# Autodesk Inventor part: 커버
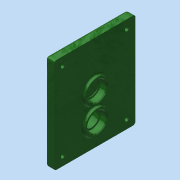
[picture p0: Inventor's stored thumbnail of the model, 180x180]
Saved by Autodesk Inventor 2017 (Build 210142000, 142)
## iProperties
Created: 2016-02
Part Number: 커버
Material: 알루미늄 6061
Document SubType Name: Modeling
Designer: mduedu
Density: 2.71 g/cm^3
Appearance: 매끄러움 - 짙은 산림 녹색
Mass: 271.622 g
Surface Area: 265.357 cm^2
Volume: 100.23 cm^3
Author: mduedu
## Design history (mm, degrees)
sketch "스케치1"
  geometry: L1 (63, 47)-(-47, 47); L2 (-47, 47)-(-47, -47); L3 (-47, -47)-(63, -47); L4 (63, -47)-(63, 47); 2 further points
  constraints: 8 end point, 2 parallel, 1 horizontal, 1 horizontal alignment, 1 midpoint, 1 perpendicular
  dimensions: "d102" = 94 distance of L3.end L1.start; "d104" = 47 distance from line of L2 point (0, 0); "d105" = 110 distance of L1.start L1.end
extrude "돌출1" new body sketch "스케치1" distance "d1" = 10; taper "d2" = 0 deg
sketch "스케치2"
  geometry: C1 r 14 at (0, 11); 1 further point
  constraints: 1 centre point, 1 vertical alignment
  dimensions: "d3" = 28 diameter of C1; "d6" = 11 distance of C1.centre point (0, 0)
extrude "돌출2" join sketch "스케치2" distance "d7" = 3; taper "d8" = 0 deg
sketch "스케치3"
  geometry: C1 r 14 at (0, -20); 1 further point
  constraints: 1 centre point, 1 vertical alignment
  dimensions: "d9" = 28 diameter of C1; "d10" = 20 distance of C1.centre point (0, 0)
extrude "돌출3" join sketch "스케치3" distance "d11" = 3; taper "d12" = 0 deg
hole "구멍1" diameter "d15" = 22; stored, may be unused: countersink angle "d19" = 90 deg, drill point angle "d21" = 0 deg; dims "d13" = 10, "d14" = 10, "d16" = 6, "d17" = 4, "d18" = 2, "d20" = 7
hole "구멍2" diameter "d24" = 18; stored, may be unused: countersink angle "d28" = 90 deg, drill point angle "d30" = 0 deg; dims "d22" = 10, "d23" = 10, "d25" = 6, "d26" = 4, "d27" = 2, "d29" = 1
hole "구멍3" diameter "d33" = 22; stored, may be unused: countersink angle "d37" = 90 deg, drill point angle "d39" = 0 deg; dims "d34" = 6, "d35" = 4, "d36" = 2, "d38" = 7, "d73" = 10, "d74" = 10
sketch "스케치4"
  geometry: C1 r 14 at (0, -20) reference; C2 r 18 at (0, -20); 1 further point
  constraints: 1 centre point, 1 coincident
  dimensions: "d40" = 36 diameter of C2
extrude "돌출4" join sketch "스케치4" distance "d41" = 4; taper "d42" = 0 deg
hole "구멍4" diameter "d45" = 22; stored, may be unused: countersink angle "d49" = 90 deg, drill point angle "d51" = 0 deg; dims "d43" = 10, "d44" = 10, "d46" = 6, "d47" = 4, "d48" = 2, "d50" = 7
hole "구멍5" diameter "d54" = 18; stored, may be unused: countersink angle "d58" = 90 deg, drill point angle "d60" = 0 deg; dims "d55" = 6, "d56" = 4, "d57" = 2, "d59" = 7, "d116" = 10, "d117" = 10
fillet "모깎기1" dims "d61" = 0.3
fillet "모깎기2" dims "d62" = 2
chamfer "모따기1" distance "d63" = 1; stored, may be unused: second distance "d64" = 2, angle "d65" = 45 deg
fillet "모깎기6" dims "d88" = 2
fillet "모깎기4" dims "d75" = 2
sketch "스케치9"
  geometry: L1 (47, 63)-(47, -47) reference; L2 (-47, 63)-(47, 63) reference; L3 (-47, -47)-(-47, 63) reference; L4 (47, -47)-(-47, -47) reference; L5 (37, 53)-(37, -37); L6 (37, -37)-(-37, -37); L7 (-37, -37)-(-37, 53); L8 (-37, 53)-(37, 53); C1 r 20 at (0, -20) reference; 5 further points
  constraints: 8 end point, 4 coincident, 3 other
  dimensions: "d107" = 10 distance between parallel lines of L8 L2
hole "구멍7" sketch "스케치9" at (-37, 53), (37, 53), (37, -37), (-37, -37) diameter "d108" = 4.5; stored, may be unused: countersink angle "d112" = 90 deg, drill point angle "d114" = 118 deg; dims "d109" = 6, "d110" = 8, "d111" = 4.6, "d113" = 8
fillet "모깎기8" dims "d106" = 3
fillet "모깎기9" dims "d115" = 3
node "솔리드1"
node "투영된 루프2"
